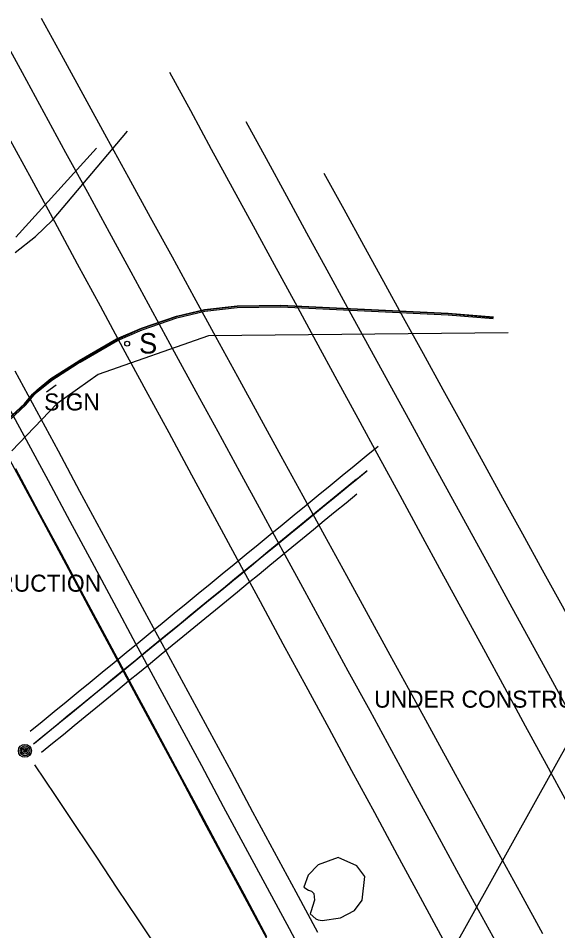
# Model space of a CAD drawing. Extents: x 368532 to 392481, y 10654822 to 10676899.
# Drawn here: x 374366.3 to 374524.6, y 10671774.3 to 10672042 of the extents above; entities that cross this region are included whole.
import ezdxf

# ---------------------------------------------------------------- set-up
doc = ezdxf.new("R2010")
doc.units = 0
for name, color, linetype in [('p_Catenary', 7, 'Continuous'), ('p_dtm stock pile', 7, 'Continuous'), ('p_road - paved curb', 7, 'Continuous'), ('p_structure constr area', 7, 'Continuous'), ('p_structure fence', 7, 'Continuous'), ('p_structure sign', 7, 'Continuous'), ('p_utility general pole', 7, 'Continuous')]:
    doc.layers.add(name, color=color, linetype=linetype)

msp = doc.modelspace()

# ---------------------------------------------------------------- linework, layer by layer
at = {"layer": 'p_Catenary'}
for points in [[(374373.01, 10672042.04), (374379.41, 10672030.37), (374385.8, 10672018.69), (374392.2, 10672007.02), (374398.6, 10671995.34), (374404.99, 10671983.67), (374411.39, 10671972), (374417.78, 10671960.32), (374424.18, 10671948.65), (374430.57, 10671936.98), (374436.97, 10671925.3), (374443.36, 10671913.63), (374449.76, 10671901.95), (374456.15, 10671890.28), (374462.55, 10671878.61), (374468.94, 10671866.93), (374475.34, 10671855.26), (374481.73, 10671843.59), (374488.13, 10671831.91), (374494.52, 10671820.24), (374500.92, 10671808.56), (374507.31, 10671796.89), (374513.71, 10671785.22), (374520.1, 10671773.54)], [(374361.06, 10672037.8), (374367.43, 10672026.1), (374373.8, 10672014.4), (374380.18, 10672002.7), (374386.55, 10671991.01), (374392.92, 10671979.31), (374399.29, 10671967.61), (374405.67, 10671955.91), (374412.04, 10671944.21), (374418.41, 10671932.52), (374424.79, 10671920.82), (374431.16, 10671909.12), (374437.53, 10671897.42), (374443.91, 10671885.72), (374450.28, 10671874.02), (374456.65, 10671862.33), (374463.02, 10671850.63), (374469.4, 10671838.93), (374475.77, 10671827.23), (374482.14, 10671815.53), (374488.52, 10671803.84), (374494.89, 10671792.14), (374501.26, 10671780.44), (374507.64, 10671768.74)], [(374410.63, 10672026.22), (374416.77, 10672014.94), (374422.92, 10672003.66), (374429.06, 10671992.38), (374435.2, 10671981.1), (374441.34, 10671969.82), (374447.49, 10671958.54), (374453.63, 10671947.26), (374459.77, 10671935.98), (374465.92, 10671924.7), (374472.06, 10671913.42), (374478.2, 10671902.14), (374484.35, 10671890.86), (374490.49, 10671879.59), (374496.63, 10671868.31), (374502.78, 10671857.03), (374508.92, 10671845.75), (374515.06, 10671834.47), (374521.2, 10671823.19), (374527.35, 10671811.91), (374533.49, 10671800.63), (374539.63, 10671789.35), (374545.78, 10671778.07), (374551.92, 10671766.79)], [(374433.02, 10672011.73), (374438.98, 10672000.85), (374444.94, 10671989.97), (374450.9, 10671979.09), (374456.86, 10671968.21), (374462.82, 10671957.33), (374468.78, 10671946.45), (374474.74, 10671935.57), (374480.7, 10671924.68), (374486.66, 10671913.8), (374492.62, 10671902.92), (374498.58, 10671892.04), (374504.54, 10671881.16), (374510.5, 10671870.28), (374516.46, 10671859.4), (374522.42, 10671848.51), (374528.38, 10671837.63), (374534.34, 10671826.75), (374540.3, 10671815.87), (374546.26, 10671804.99), (374552.22, 10671794.11), (374558.18, 10671783.23), (374564.14, 10671772.35)], [(374363.45, 10672007.19), (374370.16, 10671994.81), (374376.87, 10671982.42), (374383.57, 10671970.03), (374390.28, 10671957.64), (374396.99, 10671945.26), (374403.7, 10671932.87), (374410.41, 10671920.48), (374417.12, 10671908.1), (374423.83, 10671895.71), (374430.54, 10671883.32), (374437.24, 10671870.93), (374443.95, 10671858.55), (374450.66, 10671846.16), (374457.37, 10671833.77), (374464.08, 10671821.38), (374470.79, 10671809), (374477.5, 10671796.61), (374484.2, 10671784.22), (374490.91, 10671771.84)], [(374455.94, 10671996.61), (374461.77, 10671986.03), (374467.6, 10671975.44), (374473.42, 10671964.86), (374479.25, 10671954.28), (374485.08, 10671943.7), (374490.9, 10671933.11), (374496.73, 10671922.53), (374502.56, 10671911.95), (374508.38, 10671901.37), (374514.21, 10671890.78), (374520.04, 10671880.2), (374525.86, 10671869.62), (374531.69, 10671859.03), (374537.52, 10671848.45), (374543.34, 10671837.87), (374549.17, 10671827.29), (374555, 10671816.7), (374560.82, 10671806.12), (374566.65, 10671795.54), (374572.48, 10671784.96), (374578.3, 10671774.37), (374584.13, 10671763.79)], [(374365.24, 10671938.61), (374371.59, 10671926.85), (374377.94, 10671915.09), (374384.28, 10671903.33), (374390.63, 10671891.57), (374396.97, 10671879.81), (374403.32, 10671868.05), (374409.66, 10671856.3), (374416.01, 10671844.54), (374422.36, 10671832.78), (374428.7, 10671821.02), (374435.05, 10671809.26), (374441.39, 10671797.5), (374447.74, 10671785.74), (374454.08, 10671773.98)], [(374362.14, 10671930.34), (374368.57, 10671918.39), (374375, 10671906.44), (374381.43, 10671894.49), (374387.86, 10671882.54), (374394.29, 10671870.59), (374400.72, 10671858.63), (374407.15, 10671846.68), (374413.57, 10671834.73), (374420, 10671822.78), (374426.43, 10671810.83), (374432.86, 10671798.88), (374439.29, 10671786.92), (374445.72, 10671774.97), (374452.15, 10671763.02)], [(374440.76, 10671769.18), (374434.13, 10671781.54), (374427.5, 10671793.89), (374420.86, 10671806.24), (374414.23, 10671818.6), (374407.6, 10671830.95), (374400.97, 10671843.31), (374394.33, 10671855.66), (374387.7, 10671868.01), (374381.07, 10671880.37), (374374.43, 10671892.72), (374367.8, 10671905.08), (374361.17, 10671917.43)], [(374369.81, 10671832.86), (374373.33, 10671835.75), (374376.85, 10671838.64), (374380.37, 10671841.52), (374383.89, 10671844.41), (374387.41, 10671847.29), (374390.93, 10671850.18), (374394.45, 10671853.07), (374397.97, 10671855.95), (374401.49, 10671858.84), (374405, 10671861.72), (374408.52, 10671864.61), (374412.04, 10671867.49), (374415.56, 10671870.38), (374419.08, 10671873.27), (374422.6, 10671876.15), (374426.12, 10671879.04), (374429.64, 10671881.92), (374433.16, 10671884.81), (374436.68, 10671887.7), (374440.19, 10671890.58), (374443.71, 10671893.47), (374447.23, 10671896.35), (374450.75, 10671899.24), (374454.27, 10671902.12), (374457.79, 10671905.01), (374461.31, 10671907.9), (374464.83, 10671910.78), (374468.35, 10671913.67), (374471.87, 10671916.55)], [(374365.42, 10671909.94), (374372.12, 10671897.46), (374378.82, 10671884.98), (374385.52, 10671872.5), (374392.22, 10671860.02), (374398.92, 10671847.54), (374405.62, 10671835.06), (374412.32, 10671822.59), (374419.02, 10671810.11), (374425.72, 10671797.63), (374432.42, 10671785.15), (374439.12, 10671772.67)], [(374371, 10671829.33), (374374.36, 10671832.09), (374377.73, 10671834.85), (374381.1, 10671837.61), (374384.47, 10671840.37), (374387.84, 10671843.13), (374391.21, 10671845.89), (374394.57, 10671848.65), (374397.94, 10671851.41), (374401.31, 10671854.17), (374404.68, 10671856.93), (374408.05, 10671859.69), (374411.41, 10671862.45), (374414.78, 10671865.21), (374418.15, 10671867.97), (374421.52, 10671870.73), (374424.89, 10671873.49), (374428.26, 10671876.25), (374431.62, 10671879.01), (374434.99, 10671881.77), (374438.36, 10671884.53), (374441.73, 10671887.29), (374445.1, 10671890.04), (374448.47, 10671892.8), (374451.83, 10671895.56), (374455.2, 10671898.32), (374458.57, 10671901.08), (374461.94, 10671903.84), (374465.31, 10671906.6), (374468.68, 10671909.36)], [(374370.75, 10671829.19), (374374.11, 10671831.94), (374377.48, 10671834.7), (374380.85, 10671837.45), (374384.21, 10671840.21), (374387.58, 10671842.96), (374390.95, 10671845.72), (374394.31, 10671848.48), (374397.68, 10671851.23), (374401.05, 10671853.99), (374404.41, 10671856.74), (374407.78, 10671859.5), (374411.15, 10671862.25), (374414.51, 10671865.01), (374417.88, 10671867.77), (374421.25, 10671870.52), (374424.62, 10671873.28), (374427.98, 10671876.03), (374431.35, 10671878.79), (374434.72, 10671881.54), (374438.08, 10671884.3), (374441.45, 10671887.05), (374444.82, 10671889.81), (374448.18, 10671892.57), (374451.55, 10671895.32), (374454.92, 10671898.08), (374458.28, 10671900.83), (374461.65, 10671903.59), (374465.02, 10671906.34), (374468.38, 10671909.1)], [(374371.19, 10671829.55), (374374.44, 10671832.22), (374377.69, 10671834.89), (374380.95, 10671837.55), (374384.2, 10671840.22), (374387.45, 10671842.89), (374390.7, 10671845.56), (374393.95, 10671848.22), (374397.2, 10671850.89), (374400.46, 10671853.56), (374403.71, 10671856.22), (374406.96, 10671858.89), (374410.21, 10671861.56), (374413.46, 10671864.22), (374416.72, 10671866.89), (374419.97, 10671869.56), (374423.22, 10671872.22), (374426.47, 10671874.89), (374429.72, 10671877.56), (374432.97, 10671880.23), (374436.23, 10671882.89), (374439.48, 10671885.56), (374442.73, 10671888.23), (374445.98, 10671890.89), (374449.23, 10671893.56), (374452.48, 10671896.23), (374455.74, 10671898.89), (374458.99, 10671901.56), (374462.24, 10671904.23), (374465.49, 10671906.89)], [(374373.13, 10671826.72), (374376.32, 10671829.33), (374379.51, 10671831.95), (374382.7, 10671834.56), (374385.89, 10671837.18), (374389.08, 10671839.79), (374392.27, 10671842.4), (374395.46, 10671845.02), (374398.65, 10671847.63), (374401.84, 10671850.25), (374405.03, 10671852.86), (374408.22, 10671855.47), (374411.41, 10671858.09), (374414.6, 10671860.7), (374417.79, 10671863.32), (374420.98, 10671865.93), (374424.18, 10671868.54), (374427.37, 10671871.16), (374430.56, 10671873.77), (374433.75, 10671876.38), (374436.94, 10671879), (374440.13, 10671881.61), (374443.32, 10671884.23), (374446.51, 10671886.84), (374449.7, 10671889.45), (374452.89, 10671892.07), (374456.08, 10671894.68), (374459.27, 10671897.3), (374462.46, 10671899.91), (374465.65, 10671902.52)], [(374371.06, 10671823.02), (374377.1, 10671813.98), (374383.15, 10671804.94), (374389.19, 10671795.89), (374395.23, 10671786.85), (374401.28, 10671777.81), (374407.32, 10671768.76)]]:
    msp.add_lwpolyline(points, dxfattribs=at)
at = {"layer": 'p_dtm stock pile'}
for p, q in [((374460.13, 10671795.83), (374454.25, 10671793.73)), ((374465.61, 10671793.39), (374460.13, 10671795.83)), ((374454.25, 10671793.73), (374451.33, 10671790.67)), ((374467.99, 10671790.24), (374465.61, 10671793.39)), ((374451.33, 10671790.67), (374450.04, 10671787.09)), ((374467.19, 10671783.33), (374467.99, 10671790.24)), ((374450.04, 10671787.09), (374451.45, 10671786.3)), ((374451.45, 10671786.3), (374452.28, 10671785.93)), ((374452.28, 10671785.93), (374452.97, 10671785.29)), ((374452.97, 10671785.29), (374453.25, 10671783.28)), ((374453.25, 10671783.28), (374452.09, 10671779.92)), ((374464.91, 10671780.32), (374467.19, 10671783.33)), ((374452.09, 10671779.92), (374451.93, 10671779.31)), ((374451.93, 10671779.31), (374453.58, 10671777.88)), ((374460.82, 10671778.13), (374464.91, 10671780.32)), ((374453.58, 10671777.88), (374454.26, 10671777.54)), ((374454.26, 10671777.54), (374455.47, 10671777.4)), ((374455.47, 10671777.4), (374460.82, 10671778.13))]:
    msp.add_line(p, q, dxfattribs=at)
at = {"layer": 'p_road - paved curb'}
for p, q in [((374376.29, 10671982.81), (374398.35, 10672008.95)), ((374371.3, 10671978.06), (374376.29, 10671982.81)), ((374365.39, 10671973.34), (374371.3, 10671978.06)), ((374420.97, 10671956.63), (374430.49, 10671957.69)), ((374430.49, 10671957.69), (374443.32, 10671957.89)), ((374430.5, 10671957.54), (374443.32, 10671957.74)), ((374443.32, 10671957.89), (374492.44, 10671955.56)), ((374443.32, 10671957.74), (374492.43, 10671955.41)), ((374412.7, 10671954.68), (374420.97, 10671956.63)), ((374412.74, 10671954.54), (374421, 10671956.48)), ((374412.84, 10671954.2), (374421.06, 10671956.14)), ((374421, 10671956.48), (374430.5, 10671957.54)), ((374421.06, 10671956.14), (374430.52, 10671957.19)), ((374430.52, 10671957.19), (374443.31, 10671957.39)), ((374443.31, 10671957.39), (374492.41, 10671955.06)), ((374492.41, 10671955.06), (374505.68, 10671953.95)), ((374492.43, 10671955.41), (374505.71, 10671954.3)), ((374492.44, 10671955.56), (374505.72, 10671954.45)), ((374402.42, 10671951.14), (374412.7, 10671954.68)), ((374402.47, 10671951), (374412.74, 10671954.54)), ((374402.6, 10671950.67), (374412.84, 10671954.2)), ((374395.14, 10671947.97), (374402.42, 10671951.14)), ((374395.21, 10671947.84), (374402.47, 10671951)), ((374395.37, 10671947.52), (374402.6, 10671950.67)), ((374384.15, 10671941.62), (374395.14, 10671947.97)), ((374384.23, 10671941.49), (374395.21, 10671947.84)), ((374384.4, 10671941.19), (374395.37, 10671947.52)), ((374383.26, 10671941.08), (374384.15, 10671941.62)), ((374383.34, 10671940.95), (374384.23, 10671941.49)), ((374375.87, 10671936.32), (374383.26, 10671941.08)), ((374375.96, 10671936.2), (374383.34, 10671940.95)), ((374376.16, 10671935.91), (374383.53, 10671940.66)), ((374383.53, 10671940.66), (374384.4, 10671941.19)), ((374371.77, 10671932.99), (374375.87, 10671936.32)), ((374371.87, 10671932.88), (374375.96, 10671936.2)), ((374372.1, 10671932.61), (374376.16, 10671935.91)), ((374368.09, 10671928.93), (374370.44, 10671931.76)), ((374368.2, 10671928.83), (374370.55, 10671931.66)), ((374368.45, 10671928.59), (374370.8, 10671931.42)), ((374370.44, 10671931.76), (374371.77, 10671932.99)), ((374370.55, 10671931.66), (374371.87, 10671932.88)), ((374370.8, 10671931.42), (374372.1, 10671932.61)), ((374363.24, 10671924.42), (374368.09, 10671928.93)), ((374363.34, 10671924.31), (374368.2, 10671928.83)), ((374363.57, 10671924.04), (374368.45, 10671928.59))]:
    msp.add_line(p, q, dxfattribs=at)
at = {"layer": 'p_structure constr area'}
for p, q in [((374389.18, 10672003.89), (374365.52, 10671977.78)), ((374510, 10671949.77), (374422.05, 10671948.91)), ((374422.05, 10671948.91), (374389.72, 10671937.55)), ((374389.72, 10671937.55), (374377.55, 10671928.92)), ((374377.55, 10671928.92), (374364.43, 10671915.18))]:
    msp.add_line(p, q, dxfattribs=at)
at = {"layer": 'p_structure fence'}
msp.add_line((374483.34, 10671749.97), (374529.07, 10671832.12), dxfattribs=at)
at = {"layer": 'p_structure sign'}
msp.add_lwpolyline([(374377.39, 10671934.41), (374374.57, 10671932.32)], dxfattribs=at)
msp.add_circle((374398.24, 10671946.57), 0.713, dxfattribs=at)
at = {"layer": 'p_utility general pole'}
for radius in [1.9, 1.44, 0.973, 0.539, 0.192]:
    msp.add_circle((374368.22, 10671827.13), radius, dxfattribs=at)

# ---------------------------------------------------------------- texts
at = {"layer": 'p_structure constr area'}
for p in [(374311.09, 10671873.81), (374470.72, 10671839.79)]:
    msp.add_text('UNDER CONSTRUCTION', height=5, dxfattribs=at).set_placement(p)
at = {"layer": 'p_structure sign'}
for s, height, p in [('S', 6, (374401.7, 10671943.68)), (' SIGN', 5, (374372, 10671926.98))]:
    msp.add_text(s, height=height, dxfattribs=at).set_placement(p)

doc.saveas('drawing.dxf')
